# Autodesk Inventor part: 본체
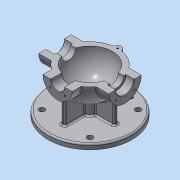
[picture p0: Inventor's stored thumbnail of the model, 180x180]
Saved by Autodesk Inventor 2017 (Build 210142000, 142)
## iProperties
Created: 2015-12
Part Number: 본체
Material: 알루미늄 6061
Document SubType Name: Modeling
Designer: mduedu
Density: 2.71 g/cm^3
Appearance: 알루미늄 - 평지
Mass: 1042.75 g
Surface Area: 959.747 cm^2
Volume: 384.779 cm^3
Author: mduedu
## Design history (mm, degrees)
sketch "스케치1"
  geometry: L1 (-53, 0)-(53, 0); A1 r 53 centre (0, 0) between (53, 0) and (-53, 0); 2 further points
  constraints: 2 coincident, 2 end point, 2 point on circle, 1 centre point, 1 horizontal, 1 midpoint
  dimensions: "d0" = 53 radius of A1
revolve "회전1" sketch "스케치1" stored, may be unused: angle "d2" = 90 deg
feature "쉘1" dims "d11" = 10
node "작업 평면1"
sketch "스케치2"
  geometry: C1 r 31 at (0, 0); 1 further point
  constraints: 1 centre point, 1 coincident
  dimensions: "d4" = 62 diameter of C1
extrude "돌출1" join sketch "스케치2" stored distance "d5" = 10; taper "d6" = 0 deg
node "작업 평면2"
sketch "스케치3"
  geometry: C1 r 28 at (0, 0); 1 further point
  constraints: 1 centre point, 1 coincident
  dimensions: "d8" = 56 diameter of C1
extrude "돌출2" join sketch "스케치3" stored distance "d9" = 10; taper "d10" = 0 deg
hole "구멍1" diameter "d14" = 35; stored, may be unused: countersink angle "d18" = 90 deg, drill point angle "d20" = 0 deg; dims "d12" = 10, "d13" = 10, "d15" = 6, "d16" = 4, "d17" = 2, "d19" = 16
hole "구멍2" diameter "d23" = 27; stored, may be unused: countersink angle "d27" = 90 deg, drill point angle "d29" = 0 deg; dims "d21" = 10, "d22" = 10, "d24" = 6, "d25" = 4, "d26" = 2, "d28" = 16
fillet "모깎기1" dims "d30" = 0.3
hole "구멍3" diameter "d33" = 26; stored, may be unused: countersink angle "d37" = 90 deg, drill point angle "d39" = 0 deg; dims "d31" = 10, "d32" = 10, "d34" = 6, "d35" = 4, "d36" = 2, "d38" = 16
chamfer "모따기1" distance "d40" = 1; stored, may be unused: second distance "d41" = 2, angle "d42" = 45 deg
sketch "스케치4"
  geometry: L1 (0, 0)-(0, -25); L2 (0, 0)-(-17.678, -17.678); A1 r 25 centre (0, 0) between (-17.678, -17.678) and (0, -25); 1 further point
  constraints: 4 end point, 2 point on circle, 1 centre point, 1 coincident, 1 vertical
  dimensions: "d43" = 50 diameter of A1; "d47" = 45 deg angle of L1 L2
hole "구멍4" sketch "스케치4" at (-17.678, -17.678) diameter "d49" = 3.242; stored, may be unused: countersink angle "d53" = 90 deg, drill point angle "d55" = 118 deg; dims "d50" = 11, "d51" = 4, "d52" = 2, "d54" = 13
sketch "스케치5"
  geometry: L1 (0, 0)-(0, -20); L2 (0, 0)-(-14.142, -14.142); A1 r 20 centre (0, 0) between (0, -20) and (-14.142, -14.142); 2 further points
  constraints: 4 end point, 2 coincident, 2 point on circle, 1 centre point, 1 vertical
  dimensions: "d59" = 40 diameter of A1; "d65" = 45 deg angle of L1 L2
hole "구멍5" sketch "스케치5" at (-14.142, -14.142) diameter "d67" = 3.242; stored, may be unused: countersink angle "d71" = 90 deg, drill point angle "d73" = 118 deg; dims "d68" = 8, "d69" = 4, "d70" = 2, "d72" = 10
node "작업 평면3"
sketch "스케치6"
  geometry: C1 r 80 at (0, 0); 1 further point
  constraints: 1 centre point, 1 coincident
  dimensions: "d78" = 160 diameter of C1
extrude "돌출3" join sketch "스케치6" distance "d80" = 10; taper "d81" = 0 deg
sketch "스케치7"
  geometry: C1 r 15 at (0, 0); 1 further point
  constraints: 1 centre point, 1 coincident
  dimensions: "d82" = 30 diameter of C1
extrude "돌출4" join sketch "스케치7" stored distance "d84" = 10; taper "d85" = 0 deg
sketch "스케치8"
  geometry: 2 further points
  constraints: 1 coincident
hole "구멍6" sketch "스케치8" at (0, 0) diameter "d86" = 20; stored, may be unused: countersink angle "d90" = 90 deg, drill point angle "d92" = 118 deg; dims "d87" = 7, "d88" = 100, "d89" = 5, "d91" = 10
fillet "모깎기2" dims "d93" = 0.3
sketch "스케치9"
  geometry: L1 (-67, -18.5)-(-66, -17.5) reference; L2 (-66, -17.5)-(-51.3, -17.5) reference; L3 (-51, -17.2)-(-51, -13.5) reference; L4 (-51, -13.5)-(-40.826, -13.5) reference; L5 (-10, -41.821)-(-10, -80) reference; L6 (-10, -80)-(-49.7, -80) reference; L7 (-50, -80.3)-(-50, -85) reference; L8 (-50, -85)-(-80, -85) reference; L9 (-80, -85)-(-80, -75) reference; L10 (-80, -75)-(-15, -75) reference; L11 (-15, -75)-(-15, -50.833) reference; L12 (-42.988, -31)-(-67, -31) reference; L13 (-67, -31)-(-67, -18.5) reference; L14 (66, -17.5)-(67, -18.5) reference; L15 (67, -18.5)-(67, -31) reference; L16 (67, -31)-(42.988, -31) reference; L17 (15, -50.833)-(15, -75) reference; L18 (15, -75)-(80, -75) reference; L19 (80, -75)-(80, -85) reference; L20 (80, -85)-(50, -85) reference; L21 (50, -85)-(50, -80.3) reference; L22 (49.7, -80)-(10, -80) reference; L23 (10, -80)-(10, -41.821) reference; L24 (40.826, -13.5)-(51, -13.5) reference; L25 (51, -13.5)-(51, -17.2) reference; L26 (51.3, -17.5)-(66, -17.5) reference; L27 (67, 18.5)-(66, 17.5) reference; L28 (66, 17.5)-(51.3, 17.5) reference; L29 (51, 17.2)-(51, 13.5) reference; L30 (51, 13.5)-(40.826, 13.5) reference; L31 (-40.826, 13.5)-(-51, 13.5) reference; L32 (-51, 13.5)-(-51, 17.2) reference; L33 (-51.3, 17.5)-(-66, 17.5) reference; L34 (-66, 17.5)-(-67, 18.5) reference; L35 (-67, 18.5)-(-67, 31) reference; L36 (-67, 31)-(-42.988, 31) reference; L37 (42.988, 31)-(67, 31) reference; L38 (67, 31)-(67, 18.5) reference; L39 (-50, -31)-(-50, -75); A1 r 0.3 centre (-51.3, -17.2) between (-51.3, -17.5) and (-51, -17.2) reference; A2 r 43 centre (0, 0) between (-40.826, -13.5) and (-10, -41.821) reference; A3 r 0.3 centre (-49.7, -80.3) between (-49.7, -80) and (-50, -80.3) reference; A4 r 53 centre (0, 0) between (-42.988, -31) and (-15, -50.833) reference; A5 r 53 centre (0, 0) between (15, -50.833) and (42.988, -31) reference; A6 r 0.3 centre (49.7, -80.3) between (50, -80.3) and (49.7, -80) reference; A7 r 43 centre (0, 0) between (10, -41.821) and (40.826, -13.5) reference; A8 r 0.3 centre (51.3, -17.2) between (51, -17.2) and (51.3, -17.5) reference; A9 r 0.3 centre (51.3, 17.2) between (51.3, 17.5) and (51, 17.2) reference; A10 r 43 centre (0, 0) between (40.826, 13.5) and (-40.826, 13.5) reference; A11 r 0.3 centre (-51.3, 17.2) between (-51, 17.2) and (-51.3, 17.5) reference; A12 r 53 centre (0, 0) between (42.988, 31) and (-42.988, 31) reference; 1 further point
  constraints: 2 end point, 2 point on line
  dimensions: "d173" = 30 distance from line of L39.end L9; "d174" = 90 deg angle of L10 L39
feature "리브1" sketch "스케치9" dims "d96" = 1, "d97" = 8, "d98" = 0, "d99" = 0, "d100" = 1, "d101" = 1
sketch "스케치14"
  geometry: L1 (-14, 62)-(-13, 61) reference; L2 (-13, 61)-(-13, 40.988) reference; L3 (-41.821, 10)-(-80, 10) reference; L4 (-80, 10)-(-80, 49.7) reference; L5 (-80.3, 50)-(-85, 50) reference; L6 (-85, 50)-(-85, 80) reference; L7 (-85, 80)-(-75, 80) reference; L8 (-75, 80)-(-75, 15) reference; L9 (-75, 15)-(-50.833, 15) reference; L10 (-28, 45)-(-28, 62) reference; L11 (-28, 62)-(-14, 62) reference; L12 (13, 61)-(14, 62) reference; L13 (14, 62)-(28, 62) reference; L14 (28, 62)-(28, 45) reference; L15 (-50.833, -15)-(-75, -15) reference; L16 (-75, -15)-(-75, -80) reference; L17 (-75, -80)-(-85, -80) reference; L18 (-85, -80)-(-85, -50) reference; L19 (-85, -50)-(-80.3, -50) reference; L20 (-80, -49.7)-(-80, -10) reference; L21 (-80, -10)-(-41.821, -10) reference; L22 (13, 40.988)-(13, 61) reference; L23 (-28, 52)-(-75, 52); A1 r 43 centre (0, 0) between (-13, 40.988) and (-41.821, 10) reference; A2 r 0.3 centre (-80.3, 49.7) between (-80, 49.7) and (-80.3, 50) reference; A3 r 53 centre (0, 0) between (-28, 45) and (-50.833, 15) reference; A4 r 53 centre (0, 0) between (0, -53) and (28, 45) reference; A5 r 53 centre (0, 0) between (-50.833, -15) and (0, -53) reference; A6 r 0.3 centre (-80.3, -49.7) between (-80.3, -50) and (-80, -49.7) reference; A7 r 43 centre (0, 0) between (-41.821, -10) and (0, -43) reference; A8 r 43 centre (0, 0) between (0, -43) and (13, 40.988) reference; 1 further point
  constraints: 2 end point, 2 point on line
  dimensions: "d175" = 28 distance of L7.end L23.end; "d176" = 90 deg angle of L8 L23
feature "리브2" sketch "스케치14" dims "d153" = 1, "d154" = 8, "d155" = 0, "d156" = 0, "d157" = 1, "d158" = 1
sketch "스케치10"
  geometry: L1 (0, 0)-(0, -65); L2 (0, 0)-(-45.962, -45.962); A1 r 65 centre (0, 0) between (0, -65) and (-45.962, -45.962); 2 further points
  constraints: 4 end point, 2 coincident, 2 point on circle, 1 centre point, 1 vertical
  dimensions: "d105" = 130 diameter of A1; "d107" = 45 deg angle of L1 L2
hole "구멍7" sketch "스케치10" at (-45.962, -45.962) diameter "d109" = 11; stored, may be unused: countersink angle "d113" = 90 deg, drill point angle "d115" = 118 deg; dims "d110" = 7, "d111" = 18, "d112" = 4, "d114" = 10
fillet "모깎기3" dims "d120" = 3
fillet "모깎기4" dims "d121" = 3, "d122" = 3
fillet "모깎기5" dims "d123" = 3
fillet "모깎기6" dims "d124" = 3
sketch "스케치11"
  geometry: C1 r 80 at (0, 0) reference; C2 r 65 at (0, 0)
  constraints: 1 centre point, 1 coincident, 1 other
  dimensions: "d161" = 130 diameter of C2
feature "엠보싱1" sketch "스케치11" dims "d11" = 10, "d125" = 0.5, "d126" = 0
sketch "스케치12"
  geometry: L1 (0, 100)-(0, -100); L2 (0, 100)-(100, 100); L3 (100, 100)-(100, -100); L4 (100, -100)-(0, -100); 2 further points
  constraints: 8 end point, 3 perpendicular, 1 coincident, 1 midpoint, 1 vertical
  dimensions: "d127" = 200 distance of L2.end L3.end; "d129" = 100 distance between parallel lines of L1 L3
extrude "돌출5" cut sketch "스케치12" stored distance "d130" = 10; taper "d131" = 0 deg
sketch "스케치13"
  geometry: C1 r 7 at (0, 53); A1 r 53 centre (0, 0) between (42.113, 32.179) and (-42.113, 32.179) reference; 1 further point
  constraints: 1 centre point, 1 point on circle
  dimensions: "d132" = 14 diameter of C1
extrude "돌출6" join sketch "스케치13" distance "d134" = 15; taper "d135" = 0 deg
hole "구멍8" diameter "d139" = 3.242; stored, may be unused: countersink angle "d143" = 90 deg, drill point angle "d145" = 118 deg; dims "d140" = 8, "d141" = 4, "d142" = 2, "d144" = 10, "d148" = 10, "d149" = 10
fillet "모깎기7" dims "d146" = 3
fillet "모깎기8" dims "d147" = 3
node "솔리드1"
mirror "대칭1"
mirror "대칭2"
pattern_circular "원형 패턴1" dims angle "d57" = 360 deg
mirror "대칭3"
pattern_circular "원형 패턴2" dims angle "d75" = 360 deg
mirror "대칭4"
pattern_circular "원형 패턴4" dims angle "d118" = 360 deg
node "절단 모서리 투영1"
node "절단 모서리 투영2"
other parameters: "d3" = 67, "d7" = 62, "d77" = -85
